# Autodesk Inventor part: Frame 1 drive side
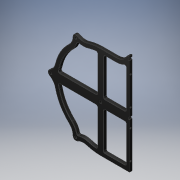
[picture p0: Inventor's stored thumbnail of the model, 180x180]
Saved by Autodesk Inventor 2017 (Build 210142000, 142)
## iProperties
Created: 2016-06
Part Number: Frame 1 drive side
Material: ABS Plastic
Document SubType Name: Modeling
Designer: Stan
Density: 1.06 g/cm^3
Appearance: Glossy - Black
Author: Stan
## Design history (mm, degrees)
sketch "Sketch1"
  geometry: L1 (9.525, 88.9)-(33.07, 88.9); L2 (0, -98.425)-(60.555, -98.425); L3 (9.525, -88.9)-(51.041, -88.9); L4 (6.35, 85.725)-(6.35, 12.7); L5 (6.35, -12.7)-(6.35, -85.725); L6 (-6.35, 85.194)-(-6.35, 12.7); L7 (-6.35, -12.7)-(-6.35, -85.194); L8 (-85.613, -9.525)-(-9.525, -9.525); L9 (9.525, -9.525)-(51.041, -9.525); L10 (-85.613, 9.525)-(-9.525, 9.525); L11 (9.525, 9.525)-(51.041, 9.525); L12 (33.07, 98.425)-(0, 98.425); L13 (54.216, 90.23)-(54.216, 12.7); L14 (54.216, -12.7)-(54.216, -85.725); L15 (60.555, 114.281)-(60.555, 110.471); L16 (60.555, 105.391)-(60.555, -98.425); C1 r 3.175 at (0, 0); C2 r 2.54 at (-104.775, 0); C3 r 2.54 at (-52.387, -90.738); C4 r 2.54 at (-52.388, 90.738); A1 r 3.175 centre (9.525, -85.725) between (6.35, -85.725) and (9.525, -88.9); A2 r 3.175 centre (9.525, 85.725) between (9.525, 88.9) and (6.35, 85.725); A3 r 3.175 centre (-9.525, -12.7) between (-6.35, -12.7) and (-9.525, -9.525); A4 r 3.175 centre (9.525, -12.7) between (9.525, -9.525) and (6.35, -12.7); A5 r 3.175 centre (51.041, -12.7) between (54.216, -12.7) and (51.041, -9.525); A6 r 3.175 centre (-9.525, 12.7) between (-9.525, 9.525) and (-6.35, 12.7); A7 r 3.175 centre (9.525, 12.7) between (6.35, 12.7) and (9.525, 9.525); A8 r 3.175 centre (51.041, 12.7) between (51.041, 9.525) and (54.216, 12.7); A9 r 98.425 centre (0, 0) between (0, 98.425) and (-29.099, 94.025); A10 r 98.425 centre (0, 0) between (-66.878, 72.213) and (-95.978, 21.812); A11 r 98.425 centre (0, 0) between (-95.978, -21.812) and (-66.878, -72.213); A12 r 98.425 centre (0, 0) between (-29.099, -94.025) and (0, -98.425); A13 r 88.9 centre (0, 0) between (-9.878, 88.35) and (-26.283, 84.926); A14 r 3.175 centre (-9.525, 85.194) between (-6.35, 85.194) and (-9.878, 88.35); A15 r 88.9 centre (0, 0) between (-60.406, 65.225) and (-86.69, 19.701); A16 r 88.9 centre (0, 0) between (-86.69, -19.701) and (-60.406, -65.225); A17 r 88.9 centre (0, 0) between (-26.283, -84.926) and (-9.878, -88.35); A18 r 3.175 centre (-9.525, -85.194) between (-9.878, -88.35) and (-6.35, -85.194); A19 r 6.35 centre (-104.775, 0) between (-107.969, 5.488) and (-107.969, -5.488); A20 r 25.4 centre (-120.746, 27.441) between (-107.969, 5.488) and (-95.978, 21.812); A21 r 34.925 centre (-120.746, 27.441) between (-88.541, 13.928) and (-86.69, 19.701); A22 r 3.175 centre (-85.613, 12.7) between (-88.541, 13.928) and (-85.613, 9.525); A23 r 25.4 centre (-120.746, -27.441) between (-95.978, -21.812) and (-107.969, -5.488); A24 r 34.925 centre (-120.746, -27.441) between (-86.69, -19.701) and (-88.541, -13.928); A25 r 3.175 centre (-85.613, -12.7) between (-85.613, -9.525) and (-88.541, -13.928); A26 r 6.35 centre (-52.387, -90.738) between (-58.737, -90.76) and (-49.232, -96.248); A27 r 25.4 centre (-84.137, -90.849) between (-58.737, -90.76) and (-66.878, -72.213); A28 r 34.925 centre (-84.137, -90.849) between (-50.239, -82.443) and (-60.406, -65.225); A29 r 3.175 centre (-47.157, -81.679) between (-50.239, -82.443) and (-46.278, -84.73); A30 r 25.4 centre (-36.609, -118.29) between (-29.099, -94.025) and (-49.232, -96.248); A31 r 34.925 centre (-36.609, -118.29) between (-26.283, -84.926) and (-46.278, -84.73); A32 r 6.35 centre (-52.388, 90.738) between (-49.232, 96.248) and (-58.737, 90.76); A33 r 25.4 centre (-36.609, 118.29) between (-49.232, 96.248) and (-29.099, 94.025); A34 r 34.925 centre (-36.609, 118.29) between (-46.278, 84.73) and (-26.283, 84.926); A35 r 3.175 centre (-47.157, 81.679) between (-46.278, 84.73) and (-50.239, 82.443); A36 r 25.4 centre (-84.137, 90.849) between (-66.878, 72.213) and (-58.737, 90.76); A37 r 34.925 centre (-84.137, 90.849) between (-60.406, 65.225) and (-50.239, 82.443); A38 r 25.4 centre (33.07, 123.825) between (33.07, 98.425) and (55.067, 111.125); A39 r 34.925 centre (33.07, 123.825) between (33.07, 88.9) and (49.544, 93.029); A40 r 3.175 centre (51.041, 90.23) between (54.216, 90.23) and (49.544, 93.029); A41 r 3.175 centre (51.041, -85.725) between (51.041, -88.9) and (54.216, -85.725); A42 r 6.35 centre (60.555, 107.931) between (60.555, 114.281) and (55.067, 111.125); A43 r 2.54 centre (60.555, 107.931) between (60.555, 110.471) and (60.555, 105.391); 1 further point
  constraints: 86 point on circle, 47 centre point, 32 end point
extrude "Extrusion1" new body sketch "Sketch1" distance "d0" = 6.35; taper "d1" = 0 deg
fillet "Fillet1" dims "d2" = 0.79375
sketch "Sketch2"
  geometry: L1 (0, 0)-(0, 203.816) reference; C1 r 1.587 at (-3.175, 177.8); C2 r 1.587 at (-3.175, 117.475); C3 r 1.587 at (-3.175, 79.375); C4 r 1.587 at (-3.175, 19.05); 3 further points
  constraints: 4 centre point
  dimensions: "d3" = 60.325 distance of C3.centre C4.centre; "d4" = 60.325 distance of C1.centre C2.centre; "d5" = 9.525 vertical distance of C2.centre point (0, 107.95); "d6" = 3.175 distance from line of L1 C1.centre; "d7" = 3.175 distance from line of L1 C2.centre; "d8" = 3.175 distance from line of L1 C3.centre; "d9" = 3.175 distance from line of L1 C4.centre; "d10" = 9.525 vertical distance of C3.centre point (0, 88.9); "d13" = 3.175 diameter of C1; "d14" = 3.175 diameter of C2; "d15" = 3.175 diameter of C3; "d16" = 3.175 diameter of C4
extrude "Extrusion2" cut sketch "Sketch2" distance "d11" = 6.35; taper "d12" = 0 deg
sketch "Sketch3"
  geometry: L1 (60.555, -97.631)-(60.555, 105.391) reference; L2 (60.555, 2.54)-(60.555, -2.54); A1 r 2.54 centre (60.555, 0) between (60.555, 2.54) and (60.555, -2.54); 1 further point
  constraints: 3 point on line, 2 end point, 2 point on circle, 1 centre point
  dimensions: "d17" = 5.08 diameter of A1
extrude "Extrusion3" cut sketch "Sketch3" distance "d18" = 6.35; taper "d19" = 0 deg
fillet "Fillet2" dims "d20" = 0.79375
body "Solid1"
